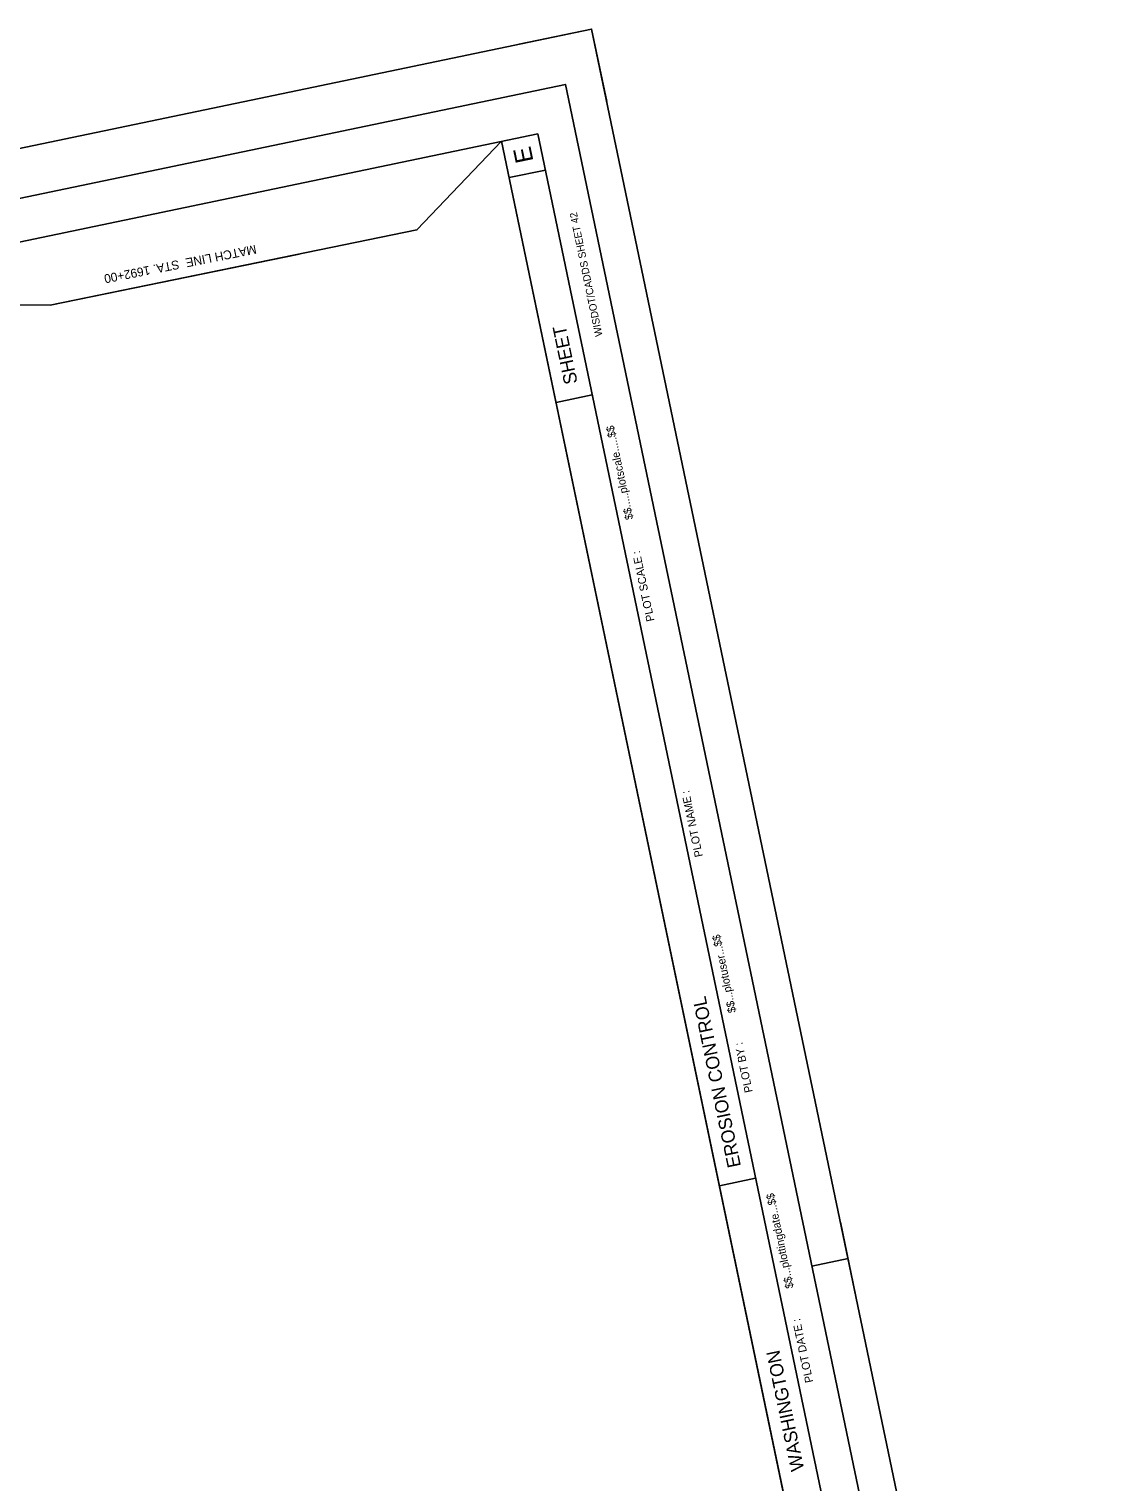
# Model space of a CAD drawing. Extents: x 361335 to 362759, y 126730 to 128619.
# Drawn here: x 362032 to 362759, y 127638 to 128619 of the extents above; entities that cross this region are included whole.
import ezdxf

# ---------------------------------------------------------------- set-up
doc = ezdxf.new("R2010")
doc.units = 0
for name, color, linetype in [('Default', 7, 'Continuous'), ('P_SHTIDX_1 [KAPUR_CADDS_LEVELS]', 7, 'Continuous'), ('P_SHTIDX_2 [KAPUR_CADDS_LEVELS]', 7, 'Continuous'), ('P_SHTIDX_3 [KAPUR_CADDS_LEVELS]', 7, 'Continuous'), ('P_TXT_Plan 1 [KAPUR_CADDS_LEVELS]', 7, 'Continuous'), ('P_TXT_Plan 2 [KAPUR_CADDS_LEVELS]', 7, 'Continuous'), ('P_TXT_Plan 3 [KAPUR_CADDS_LEVELS]', 7, 'Continuous')]:
    doc.layers.add(name, color=color, linetype=linetype)

msp = doc.modelspace()

# ---------------------------------------------------------------- linework, layer by layer
at = {"layer": 'Default'}
msp.add_lwpolyline([(361735.88, 128353.1), (361396.84, 128343.77), (361718.49, 126801.97), (362697.42, 127006.19), (362672.95, 127001.09), (362351.29, 128542.89), (362351.29, 128542.89), (362294.11, 128483.12), (362046.54, 128432.3), (361887.51, 128433.66)], close=True, dxfattribs=at)
msp.add_lwpolyline([(361735.88, 128353.1), (361396.84, 128343.77), (361718.49, 126801.97), (362697.42, 127006.19), (362672.95, 127001.09), (362351.29, 128542.89), (362351.29, 128542.89), (362294.11, 128483.12), (362046.54, 128432.3), (361887.51, 128433.66)], close=True, dxfattribs=at)
msp.add_lwpolyline([(361735.88, 128353.1), (361396.84, 128343.77), (361718.49, 126801.97), (362697.42, 127006.19), (362672.95, 127001.09), (362351.29, 128542.89), (362351.29, 128542.89), (362294.11, 128483.12), (362046.54, 128432.3), (361887.51, 128433.66)], close=True, dxfattribs=at)
msp.add_lwpolyline([(361735.88, 128353.1), (361396.84, 128343.77), (361718.49, 126801.97), (362697.42, 127006.19), (362672.95, 127001.09), (362351.29, 128542.89), (362351.29, 128542.89), (362294.11, 128483.12), (362046.54, 128432.3), (361887.51, 128433.66)], close=True, dxfattribs=at)
msp.add_lwpolyline([(361735.88, 128353.1), (361396.84, 128343.77), (361718.49, 126801.97), (362697.42, 127006.19), (362672.95, 127001.09), (362351.29, 128542.89), (362351.29, 128542.89), (362294.11, 128483.12), (362046.54, 128432.3), (361887.51, 128433.66)], close=True, dxfattribs=at)
msp.add_lwpolyline([(361735.88, 128353.1), (361396.84, 128343.77), (361718.49, 126801.97), (362697.42, 127006.19), (362672.95, 127001.09), (362351.29, 128542.89), (362351.29, 128542.89), (362294.11, 128483.12), (362046.54, 128432.3), (361887.51, 128433.66)], close=True, dxfattribs=at)
msp.add_lwpolyline([(361735.88, 128353.1), (361396.84, 128343.77), (361718.49, 126801.97), (362697.42, 127006.19), (362672.95, 127001.09), (362351.29, 128542.89), (362351.29, 128542.89), (362294.11, 128483.12), (362046.54, 128432.3), (361887.51, 128433.66)], close=True, dxfattribs=at)
msp.add_lwpolyline([(361735.88, 128353.1), (361396.84, 128343.77), (361718.49, 126801.97), (362697.42, 127006.19), (362672.95, 127001.09), (362351.29, 128542.89), (362351.29, 128542.89), (362294.11, 128483.12), (362046.54, 128432.3), (361887.51, 128433.66)], close=True, dxfattribs=at)
msp.add_lwpolyline([(361735.88, 128353.1), (361396.84, 128343.77), (361718.49, 126801.97), (362697.42, 127006.19), (362672.95, 127001.09), (362351.29, 128542.89), (362351.29, 128542.89), (362294.11, 128483.12), (362046.54, 128432.3), (361887.51, 128433.66)], close=True, dxfattribs=at)
msp.add_lwpolyline([(361735.88, 128353.1), (361396.84, 128343.77), (361718.49, 126801.97), (362697.42, 127006.19), (362672.95, 127001.09), (362351.29, 128542.89), (362351.29, 128542.89), (362294.11, 128483.12), (362046.54, 128432.3), (361887.51, 128433.66)], close=True, dxfattribs=at)
at = {"layer": 'P_SHTIDX_1 [KAPUR_CADDS_LEVELS]'}
msp.add_lwpolyline([(361682.47, 126729.84), (361335.28, 128394.01), (362412.1, 128618.66), (362759.28, 126954.49), (361682.47, 126729.84)], dxfattribs=at)
at = {"layer": 'P_SHTIDX_2 [KAPUR_CADDS_LEVELS]'}
for p, q in [((362412.1, 128618.66), (362363.15, 128608.45)), ((362422.31, 128569.71), (362412.1, 128618.66)), ((362375.77, 128548), (361396.84, 128343.77)), ((362697.42, 127006.19), (362375.77, 128548)), ((362672.95, 127001.09), (362351.29, 128542.89)), ((362380.87, 128523.52), (362356.4, 128518.42)), ((362412.53, 128371.79), (362388.05, 128366.68)), ((362522.81, 127843.17), (362498.33, 127838.07)), ((362590.29, 127764.54), (362580.08, 127813.48)), ((362585.18, 127789.01), (362560.71, 127783.91))]:
    msp.add_line(p, q, dxfattribs=at)
at = {"layer": 'P_SHTIDX_3 [KAPUR_CADDS_LEVELS]'}
for points in [[(362759.28, 126954.49), (362412.1, 128618.66), (361335.28, 128394.01), (361682.47, 126729.84)], [(362732.36, 126961.13), (362394.37, 128581.25), (361366.5, 128366.81), (361704.49, 126746.69)]]:
    msp.add_lwpolyline(points, close=True, dxfattribs=at)
at = {"layer": 'P_TXT_Plan 2 [KAPUR_CADDS_LEVELS]'}
msp.add_line((362046.54, 128432.3), (362214.73, 128466.82), dxfattribs=at)
at = {"layer": 'P_TXT_Plan 3 [KAPUR_CADDS_LEVELS]'}
msp.add_lwpolyline([(361682.47, 126729.84), (361335.28, 128394.01), (362412.1, 128618.66), (362759.28, 126954.49)], close=True, dxfattribs=at)

# ---------------------------------------------------------------- texts
at = {"layer": 'P_SHTIDX_2 [KAPUR_CADDS_LEVELS]'}
for s, height, rotation, p in [('E', 12, 101.78408, (362372.87, 128529.62)), ('WISDOT/CADDS SHEET 42', 5, 101.78408, (362419.51, 128411.75)), ('SHEET ', 9, 101.78408, (362402.65, 128379.95)), ('$$.....plotscale.....$$', 5.4, 101.78408, (362440.18, 128288.18)), ('PLOT SCALE : ', 5.4, 101.78408, (362454.52, 128219.46)), ('PLOT NAME :                      ', 5.4, 101.78408, (362487.18, 128060.48)), ('$$...plotuser...$$', 5.4, 101.78406, (362509.62, 127955.34)), ('EROSION CONTROL', 9, 101.78408, (362512.93, 127851.33)), ('PLOT BY :', 5.4, 101.78406, (362520.85, 127901.5)), ('$$...plottingdate...$$', 5.4, 101.78406, (362548.42, 127769.35)), ('PLOT DATE :', 5.4, 101.78406, (362561.7, 127705.72)), (' WASHINGTON', 9, 101.78408, (362556.33, 127643.31))]:
    msp.add_text(s, height=height, rotation=rotation, dxfattribs=at).set_placement(p)
at = {"layer": 'P_TXT_Plan 1 [KAPUR_CADDS_LEVELS]'}
msp.add_text('MATCH LINE  STA. 1692+00', height=6, rotation=191.13351, dxfattribs=at).set_placement((362185.14, 128473.1))

doc.saveas('drawing.dxf')
